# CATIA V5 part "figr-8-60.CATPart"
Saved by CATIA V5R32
Part number: Part1
Bounding box of the stored display mesh (mm): x -50.499 to 50.499, y -68.48 to 68.48, z 0 to 20
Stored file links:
  D:\PROJECTS\Project 2022\CATIA V5 6R 2022\Resources\Part Files\c08_catia_v5_6r2022_prt\figr-8-60.CATPart
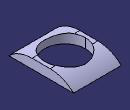
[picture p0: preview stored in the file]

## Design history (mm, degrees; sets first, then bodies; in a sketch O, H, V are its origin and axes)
Body1 (main body)
  Sketch1 on xy-plane, origin (0, 0, 0), H (1, 0, 0), V (0, 1, 0)
    line L1 (-50.499, 68.4797) -> (50.499, 68.4797)
    line L2 (50.499, 68.4797) -> (50.499, -68.4797)
    line L3 (50.499, -68.4797) -> (-50.499, -68.4797)
    line L4 (-50.499, -68.4797) -> (-50.499, 68.4797)
    axis line L5 (50.499, -68.4797) -> (-50.499, 68.4797)
    horizontal: L1 H, L3 H
    vertical: L2 V, L4 V
    midpoint: O L5
  Pad1: profile Sketch1, direction (0, 0, 1), length 20
  Fillet1: radius 71, on edge [face of Pad1 | face of Pad1]
  Fillet2: radius 71, on edge [face of Pad1 | face of Pad1]
  Body2
    Sketch2 on xy-plane, origin (0, 0, 0), H (1, 0, 0), V (0, 1, 0)
      circle A1 centre (0, 0) radius 43.2524
      point P1 (0, 43.2524)
      coincidence: A1 P1, P1 V
    Pocket1: profile Sketch2, direction (0, 0, -1), length 50, mirrored extent
  Assemble1: tool Body2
